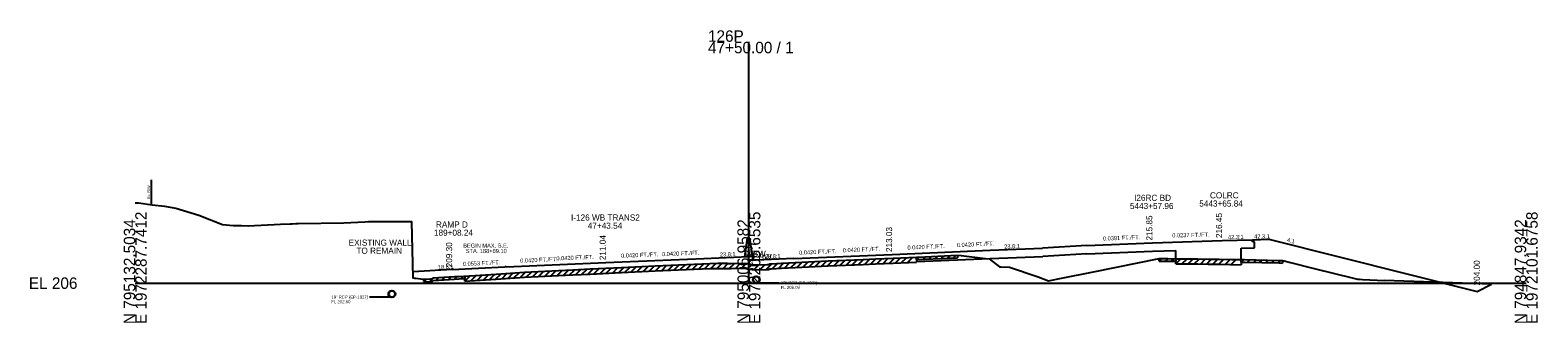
# Model space of a CAD drawing. Extents: x -161 to 1970889, y -4362 to 797231.
# Drawn here: x 1974.3 to 2342.8, y -9.7 to 61.8 of the extents above; entities that cross this region are included whole.
import ezdxf

# ---------------------------------------------------------------- set-up
doc = ezdxf.new("R2010")
doc.units = 0
for name, color, linetype in [('RD_GPK_XS_Cell', 7, 'Continuous'), ('RD_XS_Base', 7, 'Continuous'), ('RD_XS_EarthShd', 7, 'Continuous'), ('RD_XS_ExGround', 7, 'Continuous'), ('RD_XS_ExPaveRet', 7, 'Continuous'), ('RD_XS_ExRW', 7, 'Continuous'), ('RD_XS_MedBWall', 7, 'Continuous'), ('RD_XS_Misc_Line', 7, 'Continuous'), ('RD_XS_Pave', 7, 'Continuous'), ('RD_XS_PaveOvlay', 7, 'Continuous'), ('RD_XS_PaveShd', 7, 'Continuous'), ('RD_XS_Pipe', 7, 'Continuous'), ('RD_XS_TieSlope', 7, 'Continuous'), ('RD_XS_TX_Elev_EX', 7, 'Continuous'), ('RD_XS_TX_Elev_PR', 7, 'Continuous'), ('RD_XS_TX_Misc', 7, 'Continuous'), ('RD_XS_TX_MkPT', 7, 'Continuous'), ('RD_XS_TX_Notes', 7, 'Continuous'), ('RD_XS_TX_Profile', 7, 'Continuous'), ('RD_XS_TX_ShdSlope', 7, 'Continuous'), ('RD_XS_TX_Slope', 7, 'Continuous'), ('RD_XS_TX_Station', 7, 'Continuous')]:
    doc.layers.add(name, color=color, linetype=linetype)

msp = doc.modelspace()

# ---------------------------------------------------------------- linework, layer by layer
at = {"layer": 'RD_GPK_XS_Cell'}
for p, q in [((2150, 0), (2150, 58.96)), ((2000, 0), (2150, 0)), ((2150, 0), (2340, 0))]:
    msp.add_line(p, q, dxfattribs=at)
at = {"layer": 'RD_XS_Base'}
for p, q in [((2232.57, 7.18), (2248.62, 7.81)), ((2248.62, 7.8), (2254.35, 8)), ((2270.34, 8.52), (2273.57, 8.6)), ((2273.06, 10.06), (2273.06, 10.62)), ((2273.57, 10.08), (2273.06, 10.06)), ((2273.57, 8.6), (2273.57, 10.08)), ((2190.99, 5.25), (2209, 6)), ((2209, 6), (2221.82, 6.54)), ((2232.57, 7.18), (2221.82, 6.54))]:
    msp.add_line(p, q, dxfattribs=at)
at = {"layer": 'RD_XS_EarthShd'}
msp.add_line((2273.06, 10.62), (2277.11, 10.72), dxfattribs=at)
at = {"layer": 'RD_XS_ExGround'}
for p in [(2300, 0.92), (2331.49, -0.25)]:
    msp.add_line(p, (2305.33, 0.62), dxfattribs=at)
msp.add_lwpolyline([(2000, 19.59), (2000.76, 19.65), (2004.1, 19.17), (2007.12, 18.77), (2009.9, 18.34), (2015.51, 16.62), (2021.3, 14.34), (2023.9, 14.09), (2024.91, 14.07), (2025.97, 14.05), (2027.56, 14.01), (2035.52, 14.39), (2037.87, 14.51), (2038.33, 14.53), (2039.27, 14.57), (2039.85, 14.58), (2050.99, 14.72), (2056.13, 14.99), (2057, 15.03), (2057.91, 15.04), (2066.56, 15.03), (2067.51, 15.03), (2067.85, 1.27), (2068.26, 1.23), (2068.59, 1.2), (2069.83, 1.08), (2070.64, 0.99), (2072.05, 1.05), (2072.69, 1.1), (2072.84, 1.29), (2078.02, 1.59), (2079.16, 1.66), (2080.28, 1.73), (2085.63, 2.05), (2088.22, 2.22), (2095.14, 2.69), (2103.46, 3.1), (2106.95, 3.26), (2111.16, 3.47), (2118.83, 3.84), (2127.09, 4.22), (2130.94, 4.41), (2140.41, 4.79), (2142.44, 4.87), (2142.83, 4.87), (2144.69, 4.87), (2144.9, 4.8), (2145.62, 4.82), (2148.81, 4.9), (2149.58, 4.77), (2150, 4.7), (2151.53, 4.47), (2154.46, 4.57), (2154.82, 4.58), (2155.1, 4.71), (2155.44, 4.73), (2157.99, 4.91), (2161.29, 5.07), (2169.4, 5.45), (2177.91, 5.81), (2180.94, 5.93), (2185.28, 6.12), (2193, 6.46), (2200.99, 6.82), (2201.84, 6.73), (2207.82, 6.06), (2208.69, 5.98), (2211.21, 4), (2211.55, 3.98), (2213.68, 3.93), (2220.68, 1.55), (2223.26, 0.58), (2226.43, 1.21), (2234.21, 2.79), (2250.31, 6), (2252.36, 5.99), (2254.07, 5.98), (2259.76, 5.93), (2262.22, 5.9), (2264.94, 5.85), (2271.12, 5.74), (2279.64, 5.57), (2280.43, 5.55), (2280.85, 5.45), (2282.02, 5.15), (2288.19, 3.61), (2297.75, 1.23), (2298.73, 0.99), (2299.22, 0.97), (2300, 0.92)], dxfattribs=at)
at = {"layer": 'RD_XS_ExPaveRet'}
for p, q in [((2157.99, 3.66), (2161.29, 3.82)), ((2161.29, 3.82), (2169.4, 4.2)), ((2169.4, 4.2), (2177.91, 4.56)), ((2177.91, 4.56), (2180.94, 4.68)), ((2180.94, 4.68), (2185.28, 4.87)), ((2185.28, 4.87), (2190.99, 5.12)), ((2190.99, 6.37), (2190.99, 5.12)), ((2190.99, 5.75), (2190.99, 6.37)), ((2190.99, 5.75), (2193, 5.84)), ((2193, 5.84), (2200.99, 6.2)), ((2200.99, 6.82), (2200.99, 6.2)), ((2250.31, 5.37), (2250.31, 6)), ((2250.31, 5.37), (2252.36, 5.36)), ((2252.36, 5.36), (2254.07, 5.35)), ((2254.07, 5.35), (2254.35, 5.35)), ((2254.35, 4.72), (2254.35, 5.97)), ((2254.35, 5.97), (2254.35, 5.35)), ((2254.35, 4.72), (2259.76, 4.68)), ((2259.76, 4.68), (2262.22, 4.65)), ((2262.22, 4.65), (2264.94, 4.6)), ((2264.94, 4.6), (2270.34, 4.51)), ((2270.34, 5.76), (2270.34, 4.51)), ((2270.34, 5.13), (2270.34, 5.76)), ((2270.34, 5.13), (2271.12, 5.12)), ((2271.12, 5.12), (2279.64, 4.94)), ((2279.64, 4.94), (2280.43, 4.92)), ((2280.43, 5.55), (2280.43, 4.92)), ((2070.53, 0.37), (2070.53, 1)), ((2070.53, 0.37), (2070.64, 0.36)), ((2070.64, 0.36), (2072.05, 0.42)), ((2072.05, 0.42), (2072.69, 0.47)), ((2072.69, 0.47), (2072.84, 0.66)), ((2072.84, 0.66), (2078.02, 0.97)), ((2078.02, 0.97), (2079.16, 1.03)), ((2079.16, 1.03), (2080.28, 1.1)), ((2080.28, 1.1), (2080.55, 1.12)), ((2080.55, 0.49), (2080.55, 1.74)), ((2080.55, 1.74), (2080.55, 1.12)), ((2080.55, 0.49), (2085.63, 0.8)), ((2085.63, 0.8), (2088.22, 0.97)), ((2088.22, 0.97), (2095.14, 1.44)), ((2095.14, 1.44), (2103.46, 1.85)), ((2103.46, 1.85), (2106.95, 2.01)), ((2106.95, 2.01), (2111.16, 2.22)), ((2111.16, 2.22), (2118.83, 2.59)), ((2118.83, 2.59), (2127.09, 2.97)), ((2127.09, 2.97), (2130.94, 3.16)), ((2130.94, 3.16), (2140.41, 3.54)), ((2140.41, 3.54), (2142.44, 3.62)), ((2142.44, 3.62), (2142.83, 3.62)), ((2142.83, 3.62), (2144.69, 3.62)), ((2144.69, 3.62), (2144.9, 3.55)), ((2144.9, 3.55), (2145.62, 3.57)), ((2145.62, 3.57), (2148.81, 3.65)), ((2148.81, 3.65), (2149.58, 3.52)), ((2149.58, 3.52), (2150, 3.45)), ((2150, 3.45), (2151.53, 3.22)), ((2151.53, 3.22), (2154.46, 3.32)), ((2154.46, 3.32), (2154.82, 3.33)), ((2154.82, 3.33), (2155.1, 3.46)), ((2155.1, 3.46), (2155.44, 3.48)), ((2155.44, 3.48), (2157.99, 3.66))]:
    msp.add_line(p, q, dxfattribs=at)
at = {"layer": 'RD_XS_ExRW'}
msp.add_line((2003.85, 25.21), (2003.85, 19.21), dxfattribs=at)
at = {"layer": 'RD_XS_MedBWall'}
for p, q in [((2149, 6.47), (2149.67, 11.01)), ((2150.19, 11.01), (2149.67, 11.01)), ((2151, 5.61), (2150.19, 11.01))]:
    msp.add_line(p, q, dxfattribs=at)
at = {"layer": 'RD_XS_Misc_Line'}
for p, q in [((2115.12, 2.41), (2116.43, 3.72)), ((2116.62, 2.48), (2117.93, 3.79)), ((2118.12, 2.55), (2119.44, 3.86)), ((2119.62, 2.62), (2120.94, 3.94)), ((2121.13, 2.69), (2122.44, 4.01)), ((2122.63, 2.76), (2123.94, 4.08)), ((2124.13, 2.84), (2125.45, 4.15)), ((2125.64, 2.91), (2126.95, 4.22)), ((2127.14, 2.98), (2128.45, 4.29)), ((2128.64, 3.05), (2129.96, 4.36)), ((2130.14, 3.12), (2131.46, 4.43)), ((2131.65, 3.19), (2132.95, 4.49)), ((2133.15, 3.25), (2134.46, 4.55)), ((2134.65, 3.31), (2135.96, 4.61)), ((2136.16, 3.37), (2137.46, 4.67)), ((2137.66, 3.43), (2138.96, 4.73)), ((2139.16, 3.49), (2140.47, 4.79)), ((2140.67, 3.55), (2141.97, 4.85)), ((2142.17, 3.61), (2143.43, 4.87)), ((2143.67, 3.62), (2144.87, 4.81)), ((2145.17, 3.56), (2146.46, 4.84)), ((2146.68, 3.6), (2147.96, 4.88)), ((2148.18, 3.63), (2149.35, 4.81)), ((2149.68, 3.5), (2150.77, 4.59)), ((2151.19, 3.27), (2152.41, 4.5)), ((2152.69, 3.26), (2153.98, 4.55)), ((2154.19, 3.31), (2155.63, 4.75)), ((2155.69, 3.5), (2157.04, 4.85)), ((2157.2, 3.61), (2158.53, 4.94)), ((2158.7, 3.7), (2160.01, 5.01)), ((2160.2, 3.77), (2161.52, 5.08)), ((2161.71, 3.84), (2163.02, 5.15)), ((2163.21, 3.91), (2164.52, 5.22)), ((2164.71, 3.98), (2166.03, 5.29)), ((2166.21, 4.05), (2167.53, 5.37)), ((2167.72, 4.13), (2169.03, 5.44)), ((2169.22, 4.2), (2170.53, 5.5)), ((2170.72, 4.26), (2172.03, 5.56)), ((2172.23, 4.32), (2173.53, 5.63)), ((2173.73, 4.38), (2175.04, 5.69)), ((2175.23, 4.45), (2176.54, 5.75)), ((2176.73, 4.51), (2178.04, 5.81)), ((2178.24, 4.57), (2179.54, 5.88)), ((2179.74, 4.63), (2181.05, 5.94)), ((2181.24, 4.7), (2182.55, 6)), ((2182.75, 4.76), (2184.06, 6.07)), ((2184.25, 4.83), (2185.56, 6.14)), ((2185.75, 4.89), (2187.06, 6.2)), ((2187.25, 4.96), (2188.56, 6.27)), ((2188.76, 5.03), (2190.07, 6.33)), ((2190.99, 5.75), (2191.65, 6.4)), ((2192.5, 5.81), (2193.15, 6.47)), ((2194, 5.88), (2194.66, 6.54)), ((2195.5, 5.95), (2196.16, 6.6)), ((2197.01, 6.02), (2197.66, 6.67)), ((2198.51, 6.08), (2199.16, 6.74)), ((2200.01, 6.15), (2200.67, 6.81)), ((2250.31, 5.37), (2250.93, 5.99)), ((2251.81, 5.37), (2252.44, 5.99)), ((2253.32, 5.36), (2253.94, 5.98)), ((2254.35, 4.72), (2255.59, 5.96)), ((2255.85, 4.71), (2257.09, 5.95)), ((2257.35, 4.7), (2258.59, 5.94)), ((2258.86, 4.68), (2260.1, 5.92)), ((2260.36, 4.67), (2261.6, 5.91)), ((2261.86, 4.65), (2263.1, 5.88)), ((2263.37, 4.63), (2264.6, 5.86)), ((2264.87, 4.61), (2266.1, 5.83)), ((2266.37, 4.58), (2267.6, 5.81)), ((2267.87, 4.55), (2269.1, 5.78)), ((2270.34, 5.13), (2270.95, 5.75)), ((2271.84, 5.1), (2272.45, 5.72)), ((2273.34, 5.07), (2273.96, 5.68)), ((2274.84, 5.04), (2275.46, 5.65)), ((2276.35, 5.01), (2276.96, 5.62)), ((2277.85, 4.98), (2278.46, 5.59)), ((2279.35, 4.95), (2279.97, 5.56)), ((2070.53, 0.37), (2071.17, 1.01)), ((2072.03, 0.42), (2072.9, 1.29)), ((2073.54, 0.7), (2074.2, 1.37)), ((2075.04, 0.79), (2075.7, 1.45)), ((2076.54, 0.88), (2077.21, 1.54)), ((2078.04, 0.97), (2078.71, 1.63)), ((2079.55, 1.06), (2080.22, 1.72)), ((2080.55, 0.49), (2081.88, 1.82)), ((2082.05, 0.58), (2083.39, 1.92)), ((2083.56, 0.68), (2084.89, 2.01)), ((2085.06, 0.77), (2086.4, 2.1)), ((2086.56, 0.86), (2087.9, 2.2)), ((2088.06, 0.96), (2089.41, 2.3)), ((2089.57, 1.06), (2090.91, 2.4)), ((2091.07, 1.16), (2092.41, 2.5)), ((2092.57, 1.27), (2093.92, 2.61)), ((2094.08, 1.37), (2095.41, 2.7)), ((2095.58, 1.46), (2096.9, 2.78)), ((2097.08, 1.53), (2098.4, 2.85)), ((2098.58, 1.61), (2099.9, 2.92)), ((2100.09, 1.68), (2101.4, 3)), ((2101.59, 1.76), (2102.91, 3.07)), ((2103.09, 1.83), (2104.41, 3.14)), ((2104.6, 1.9), (2105.91, 3.21)), ((2106.1, 1.97), (2107.41, 3.28)), ((2107.6, 2.04), (2108.92, 3.36)), ((2109.1, 2.12), (2110.42, 3.43)), ((2110.61, 2.19), (2111.92, 3.5)), ((2112.11, 2.26), (2113.43, 3.58)), ((2113.61, 2.34), (2114.93, 3.65))]:
    msp.add_line(p, q, dxfattribs=at)
at = {"layer": 'RD_XS_Pave'}
for p, q in [((2185, 7.03), (2209, 8.04)), ((2232.57, 9.22), (2248.62, 9.85)), ((2248.62, 9.85), (2265.66, 10.45)), ((2077.46, 3.3), (2090.36, 4.02)), ((2090.7, 4.02), (2115, 5.04)), ((2115, 5.04), (2139, 6.05)), ((2161, 6.03), (2185, 7.03))]:
    msp.add_line(p, q, dxfattribs=at)
at = {"layer": 'RD_XS_PaveOvlay'}
for p, q in [((2254.35, 5.97), (2254.35, 8)), ((2270.34, 5.76), (2270.34, 8.52)), ((2111.16, 3.47), (2118.83, 3.84)), ((2118.83, 3.84), (2127.09, 4.22)), ((2127.09, 4.22), (2130.94, 4.41)), ((2130.94, 4.41), (2140.41, 4.79)), ((2140.41, 4.79), (2142.44, 4.87)), ((2142.44, 4.87), (2142.83, 4.87)), ((2142.83, 4.87), (2144.69, 4.87)), ((2144.69, 4.87), (2144.9, 4.8)), ((2144.9, 4.8), (2145.62, 4.82)), ((2145.62, 4.82), (2148.81, 4.9)), ((2148.81, 4.9), (2149.58, 4.77)), ((2149.58, 4.77), (2150, 4.7)), ((2150, 4.7), (2151.53, 4.47)), ((2151.53, 4.47), (2154.46, 4.57)), ((2154.46, 4.57), (2154.82, 4.58)), ((2154.82, 4.58), (2155.1, 4.71)), ((2155.1, 4.71), (2155.44, 4.73)), ((2155.44, 4.73), (2157.99, 4.91)), ((2157.99, 4.91), (2161.29, 5.07)), ((2161.29, 5.07), (2169.4, 5.45)), ((2169.4, 5.45), (2177.91, 5.81)), ((2177.91, 5.81), (2180.94, 5.93)), ((2180.94, 5.93), (2185.28, 6.12)), ((2185.28, 6.12), (2190.99, 6.37)), ((2190.99, 6.37), (2190.99, 5.25)), ((2254.35, 5.97), (2259.76, 5.93)), ((2259.76, 5.93), (2263.58, 5.88)), ((2263.58, 5.88), (2268.03, 5.8)), ((2268.03, 5.8), (2270.34, 5.76)), ((2080.55, 1.74), (2085.63, 2.05)), ((2085.63, 2.05), (2088.22, 2.22)), ((2088.22, 2.22), (2095.14, 2.69)), ((2095.14, 2.69), (2103.46, 3.1)), ((2103.46, 3.1), (2106.95, 3.26)), ((2106.95, 3.26), (2111.16, 3.47))]:
    msp.add_line(p, q, dxfattribs=at)
msp.add_lwpolyline([(2067.81, 2.79), (2067.85, 1.27), (2068.26, 1.23), (2068.59, 1.2), (2069.83, 1.08), (2070.64, 0.99), (2072.05, 1.05), (2072.69, 1.1), (2072.84, 1.29), (2078.02, 1.59), (2079.16, 1.66), (2080.28, 1.73), (2080.55, 1.74)], dxfattribs=at)
at = {"layer": 'RD_XS_PaveShd'}
for p, q in [((2209, 8.04), (2221.73, 8.58)), ((2232.57, 9.22), (2221.73, 8.58)), ((2265.66, 10.45), (2273.06, 10.62)), ((2090.7, 4.02), (2090.36, 4.02)), ((2139, 6.05), (2150, 6.51)), ((2150, 5.56), (2150, 6.51)), ((2161, 6.03), (2150, 5.56)), ((2077.46, 3.3), (2067.81, 2.79))]:
    msp.add_line(p, q, dxfattribs=at)
at = {"layer": 'RD_XS_Pipe'}
for p, q in [((2152.29, 0.09), (2157.29, 0.09)), ((2062.22, -3.4), (2057.22, -3.4))]:
    msp.add_line(p, q, dxfattribs=at)
for centre, radius in [((2151.79, 0.84), 0.85), ((2151.79, 0.84), 0.75), ((2062.72, -2.65), 0.85), ((2062.72, -2.65), 0.75)]:
    msp.add_circle(centre, radius, dxfattribs=at)
at = {"layer": 'RD_XS_TieSlope'}
for p, q in [((2277.11, 10.72), (2327.99, -2)), ((2327.99, -2), (2331.49, -0.25))]:
    msp.add_line(p, q, dxfattribs=at)

# ---------------------------------------------------------------- texts
at = {"layer": 'RD_GPK_XS_Cell'}
for s, p in [('47+50.00 / 1', (2140, 56.16)), ('126P', (2140, 58.96)), ('EL 206', (1974, -1.4))]:
    msp.add_text(s, height=2.8, dxfattribs=at).set_placement(p)
for s, p in [('N 795132.5034', (2000, -10)), ('E 1972287.7412', (2002.8, -10)), ('N 795006.9582', (2150, -10)), ('E 1972205.6535', (2152.8, -10)), ('N 794847.9342', (2340, -10)), ('E 1972101.6758', (2342.8, -10))]:
    msp.add_text(s, height=2.8, rotation=90, dxfattribs=at).set_placement(p)
at = {"layer": 'RD_XS_ExRW'}
msp.add_text('Ex. R/W ', height=0.65, rotation=90, dxfattribs=at).set_placement((2003.6, 20.59))
at = {"layer": 'RD_XS_Pipe'}
for s, p in [('18" RCP (EP-1931)', (2157.79, -0.29)), ('18" RCP (EP-1927)', (2047.93, -3.77)), ('FL 206.09', (2157.79, -1.41)), ('FL 202.60', (2047.93, -4.9))]:
    msp.add_text(s, height=0.75, dxfattribs=at).set_placement(p)
at = {"layer": 'RD_XS_TX_Elev_EX'}
msp.add_text('210.70', height=1, rotation=90, dxfattribs=at).set_placement((2151, 4.7))
at = {"layer": 'RD_XS_TX_Elev_PR'}
for s, p in [(' 215.85', (2248.62, 9.85)), (' 216.45', (2265.66, 10.45)), (' 211.04', (2115, 5.04)), (' 213.03', (2185, 7.03)), (' 209.30', (2077.46, 3.3))]:
    msp.add_text(s, height=1.5, rotation=90, dxfattribs=at).set_placement(p)
at = {"layer": 'RD_XS_TX_Misc'}
msp.add_text('204.00', height=1.5, rotation=90, dxfattribs=at).set_placement((2328.67, -0.56))
at = {"layer": 'RD_XS_TX_MkPT'}
for s, p in [('WBW', (2149, 6.47)), ('EBW', (2151, 5.61))]:
    msp.add_text(s, height=1.5, dxfattribs=at).set_placement(p)
at = {"layer": 'RD_XS_TX_Notes'}
for s, height, p in [('EXISTING WALL', 1.5, (2052.16, 9.15)), ('TO REMAIN', 1.5, (2054.05, 7.18)), ('BEGIN MAX. S.E.', 1, (2080.16, 8.68)), ('STA. 188+89.10', 1, (2080.78, 7.37))]:
    msp.add_text(s, height=height, dxfattribs=at).set_placement(p)
at = {"layer": 'RD_XS_TX_Profile'}
for p in [(2142.91, 6.47), (2212.41, 8.43), (2153.91, 5.98)]:
    msp.add_text('23.8:1', height=1, rotation=2.405, dxfattribs=at).set_placement(p)
at = {"layer": 'RD_XS_TX_ShdSlope'}
msp.add_text('42.3:1', height=1, rotation=1.3553, dxfattribs=at).set_placement((2273.5, 10.88))
at = {"layer": 'RD_XS_TX_Slope'}
for s, rotation, p in [('0.0391 FT./FT.', 2.2414, (2236.54, 10.38)), ('0.0237 FT./FT.', 1.3554, (2253.49, 11.16)), ('42.3:1', 1.3553, (2267.11, 10.73)), ('0.0420 FT./FT.', 2.405, (2118.77, 6.2)), ('0.0420 FT./FT.', 2.405, (2128.77, 6.58)), ('0.0420 FT./FT.', 2.405, (2162.28, 6.95)), ('0.0420 FT./FT.', 2.405, (2172.96, 7.53)), ('0.0420 FT./FT.', 2.405, (2188.77, 8.19)), ('0.0420 FT./FT.', 2.405, (2200.85, 8.8)), ('4:1', 344.1175, (2281.44, 10.17)), ('18.8:1', 3.0514, (2073.97, 3.37)), ('0.0553 FT./FT.', 2.405, (2080.1, 4.19)), ('0.0420 FT./FT.', 2.405, (2094.11, 4.99)), ('0.0420 FT./FT.', 2.405, (2102.96, 5.54))]:
    msp.add_text(s, height=1, rotation=rotation, dxfattribs=at).set_placement(p)
at = {"layer": 'RD_XS_TX_Station'}
for s, p in [('COLRC', (2262.69, 20.7)), ('COLRC', (2262.69, 20.7)), ('5443+57.96', (2243.13, 18.1)), ('I26RC BD', (2244.15, 20.1)), ('5443+65.84', (2260.08, 18.7)), ('5443+65.84', (2260.08, 18.7)), ('RAMP D', (2073.5, 13.58)), ('I-126 WB TRANS2', (2106.51, 15.29)), ('47+43.54', (2110.61, 13.29)), ('189+08.24', (2073.01, 11.58))]:
    msp.add_text(s, height=1.5, dxfattribs=at).set_placement(p)

doc.saveas('drawing.dxf')
